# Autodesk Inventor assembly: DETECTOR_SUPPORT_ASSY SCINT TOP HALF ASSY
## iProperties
Shininess: 64.0
Length Units: 11272
Angle Units: 11279
Time Units: 11290
Mass Units: 11286
Length Display Precision: 3
Angle Display Precision: 2
Compacted: True
Part Number: DETECTOR_SUPPORT_ASSY SCINT TOP HALF ASSY
Document SubType Name: Assembly
Created: 2004-08
Designer: John Blackburn
Manufacturer: Standard
Standards Organization: Custom
Density: 0.0
Volumn: 0.0
Area: 0.0
PropertySet Name: Model Information
Control State: 0
Master: False
Checked Out: False
Author: John Blackburn
